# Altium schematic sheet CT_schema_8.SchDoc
size 297 x 239 mm
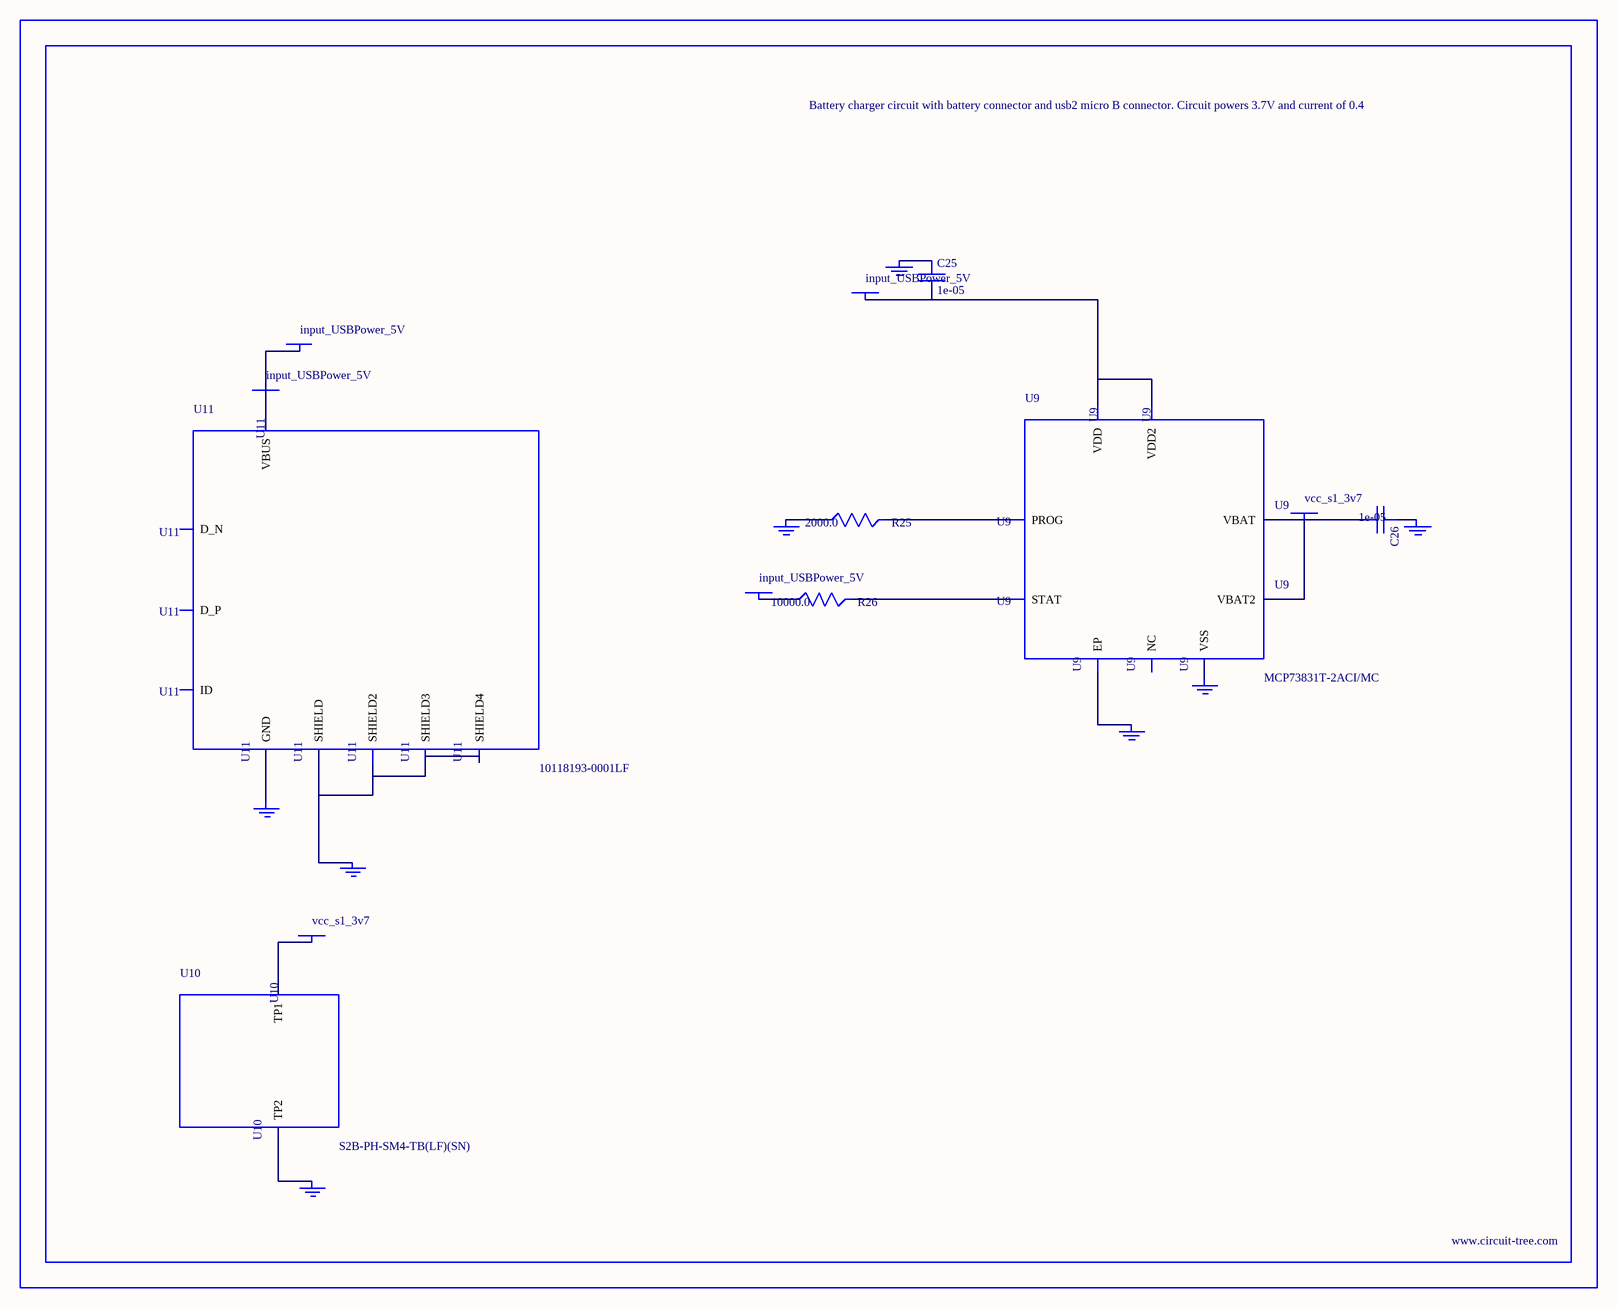
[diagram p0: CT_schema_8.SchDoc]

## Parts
BORDER7  (no value)
C25  1e-05  [C1206]
C26  1e-05  [C1206]
GND_INSTANCE_7_0  (no value)
GND_INSTANCE_7_1  (no value)
GND_INSTANCE_7_2  (no value)
GND_INSTANCE_7_3  (no value)
GND_INSTANCE_7_4  (no value)
GND_INSTANCE_7_5  (no value)
GND_INSTANCE_7_6  (no value)
GND_INSTANCE_7_7  (no value)
POWER_INSTANCE_7_0  input_USBPower_5V
POWER_INSTANCE_7_1  input_USBPower_5V
POWER_INSTANCE_7_2  vcc_s1_3v7
POWER_INSTANCE_7_3  vcc_s1_3v7
POWER_INSTANCE_7_4  input_USBPower_5V
POWER_INSTANCE_7_5  input_USBPower_5V
R25  2000.0  [R0603]
R26  10000.0  [R0603]
U9  MCP73831T-2ACI/MC  [DFN8_2X3MC]
U10  S2B-PH-SM4-TB(LF)(SN)  [JST-2-SMD]
U11  10118193-0001LF  [FCI_10118193-0001LF]

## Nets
NetC25_1: C25.1 GND_INSTANCE_7_0.0(GND)
NetC25_2: C25.2 POWER_INSTANCE_7_0.0(PWR) U9.1(VDD) U9.2(VDD2)
NetC26_1: C26.1 GND_INSTANCE_7_1.0(GND)
NetC26_2: C26.2 POWER_INSTANCE_7_2.0(PWR) U9.3(VBAT) U9.4(VBAT2)
NetGND_INSTANCE_7_2_0: GND_INSTANCE_7_2.0(GND) R25.1
NetGND_INSTANCE_7_3_0: GND_INSTANCE_7_3.0(GND) U9.9(EP)
NetGND_INSTANCE_7_4_0: GND_INSTANCE_7_4.0(GND) U9.6(VSS)
NetGND_INSTANCE_7_5_0: GND_INSTANCE_7_5.0(GND) U10.2(TP2)
NetGND_INSTANCE_7_6_0: GND_INSTANCE_7_6.0(GND) U11.6(SHIELD) U11.7(SHIELD2) U11.8(SHIELD3) U11.9(SHIELD4)
NetGND_INSTANCE_7_7_0: GND_INSTANCE_7_7.0(GND) U11.5(GND)
NetPOWER_INSTANCE_7_1_0: POWER_INSTANCE_7_1.0(PWR) R26.1
NetPOWER_INSTANCE_7_3_0: POWER_INSTANCE_7_3.0(PWR) U10.1(TP1)
NetPOWER_INSTANCE_7_4_0: POWER_INSTANCE_7_4.0(PWR) POWER_INSTANCE_7_5.0(PWR) U11.1(VBUS)
NetR25_2: R25.2 U9.8(PROG)
NetR26_2: R26.2 U9.5(STAT)

Not connected (* = marked no-connect by the designer): U9 7(NC); U11 2(D_N) 3(D_P) 4(ID)

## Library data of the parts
BORDER7 = BORDER_PAGE7
C25 C26 = C1206C106K3RACTU
GND_INSTANCE_7_0-GND_INSTANCE_7_7 = GND
POWER_INSTANCE_7_0-POWER_INSTANCE_7_5 = PWR
R25 = RC0603JR-072KL
R26 = RC0603JR-0710KL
